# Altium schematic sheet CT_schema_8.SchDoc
size 274 x 160 mm
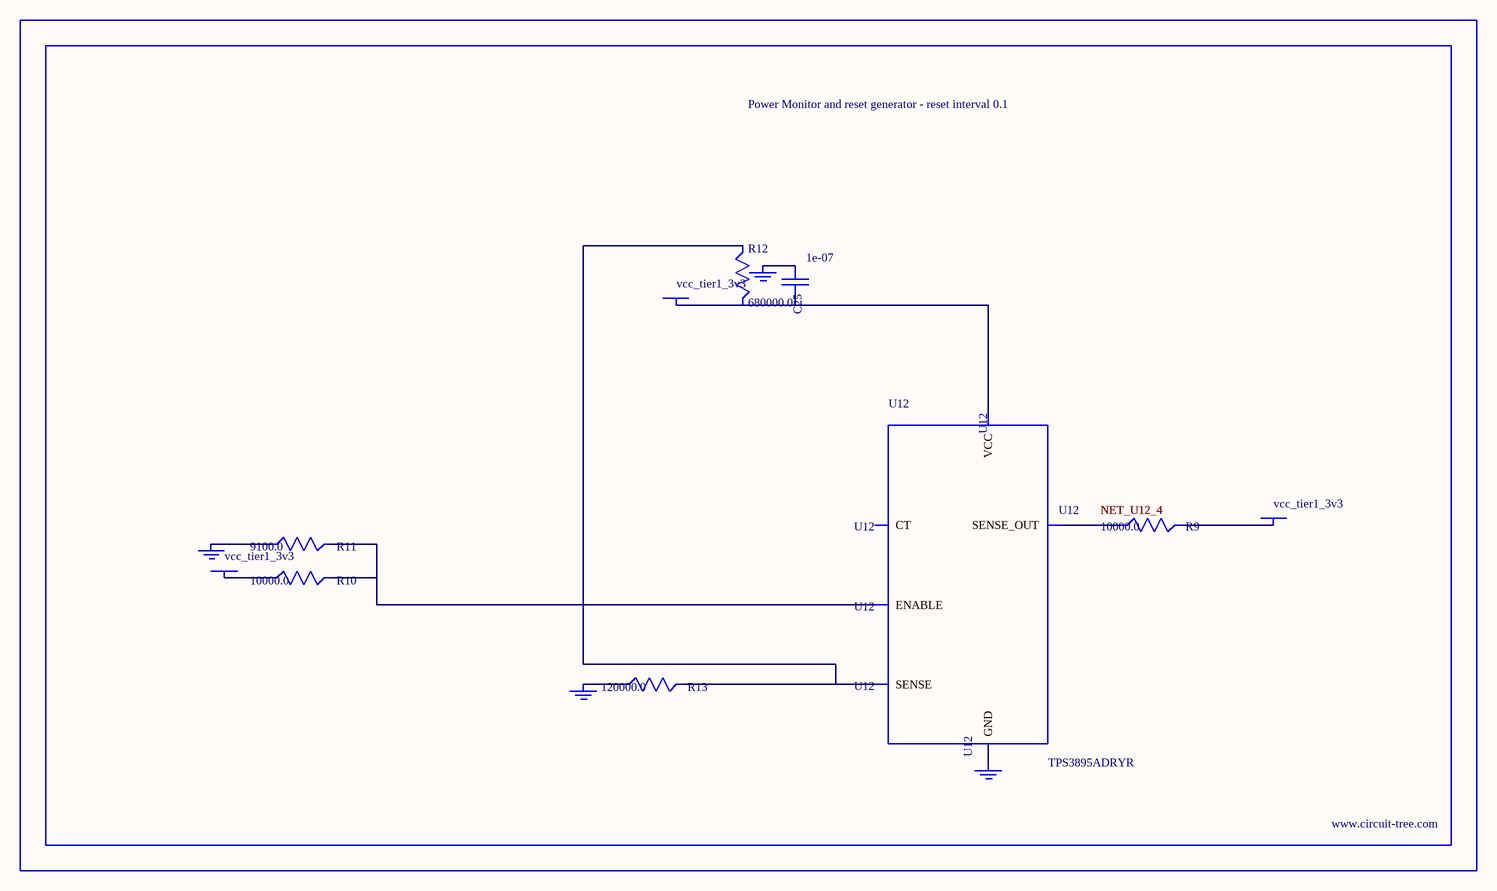
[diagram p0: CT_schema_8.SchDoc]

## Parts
BORDER7  (no value)
C25  1e-07  [C0402]
GND_INSTANCE_7_0  (no value)
GND_INSTANCE_7_1  (no value)
GND_INSTANCE_7_2  (no value)
GND_INSTANCE_7_3  (no value)
POWER_INSTANCE_7_0  vcc_tier1_3v3
POWER_INSTANCE_7_1  vcc_tier1_3v3
POWER_INSTANCE_7_2  vcc_tier1_3v3
R9  10000.0  [R0603]
R10  10000.0  [R0603]
R11  9100.0  [R0603]
R12  680000.0  [R0603]
R13  120000.0  [R0603]
U12  TPS3895ADRYR  [SON-6]

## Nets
NetC25_1: C25.1 GND_INSTANCE_7_2.0(GND)
NetC25_2: C25.2 POWER_INSTANCE_7_2.0(PWR) R12.2 U12.6(VCC)
NetGND_INSTANCE_7_0_0: GND_INSTANCE_7_0.0(GND) R11.1
NetGND_INSTANCE_7_1_0: GND_INSTANCE_7_1.0(GND) R13.1
NetGND_INSTANCE_7_3_0: GND_INSTANCE_7_3.0(GND) U12.2(GND)
NetPOWER_INSTANCE_7_0_0: POWER_INSTANCE_7_0.0(PWR) R10.1
NetPOWER_INSTANCE_7_1_0: POWER_INSTANCE_7_1.0(PWR) R9.2
NetR9_1: R9.1 U12.4(SENSE_OUT)
NetR10_2: R10.2 R11.2 U12.1(ENABLE)
NetR12_1: R12.1 R13.2 U12.3(SENSE)

Not connected (* = marked no-connect by the designer): U12 5(CT)

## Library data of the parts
BORDER7 = BORDER_PAGE7
C25 = C0402C104K3RACTU
GND_INSTANCE_7_0-GND_INSTANCE_7_3 = GND
POWER_INSTANCE_7_0-POWER_INSTANCE_7_2 = PWR
R9 R10 = RC0603JR-0710KL
R11 = RC0603JR-079K1L
R12 = RC0603JR-07680KL
R13 = RC0603JR-07120KL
